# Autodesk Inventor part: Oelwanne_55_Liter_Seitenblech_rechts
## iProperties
Created: 2005-05
Part Number: Oelwanne_55_Liter_Seitenblech_rechts
Material: Stahl (schweißbar)
Document SubType Name: Sheet Metal
Designer: Mario
Manufacturer: Standard
Standards Organization: Custom
Author: Mario
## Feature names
1. Extrusion2
2. Abgeleiteter Körper1 [Tagging]
